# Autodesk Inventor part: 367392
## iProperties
Created: 2006-08
Part Number: 367392
Material: 45H vz
Description: Gewindestift
Vendor: Autodesk Inc.
Document SubType Name: Modeling
Standard: DIN 913
Designer: I.Baliuc
Standards Organization: DIN
Language: de-DE
Size Designation: M6 x 16
Categories: <MemberInstance Version="R10.0.0"><Categories><Category DisplayName="Schrauben" InternalName="e4da775c-781d-43d5-af7c-5136215cf5a6" Mnemonic="FSTN"><Category Di
Density: 7.86 g/cm^3
Abmessung: M6 x 16
Author: T.Messerschmitt
Comments: DIN 913 - M6 x 16
Revision Number: 367392
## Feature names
1. Körper [Revolution]
2. Loch [Extrusion]
3. Fase1 [Chamfer]
4. Fase2 [Chamfer]
